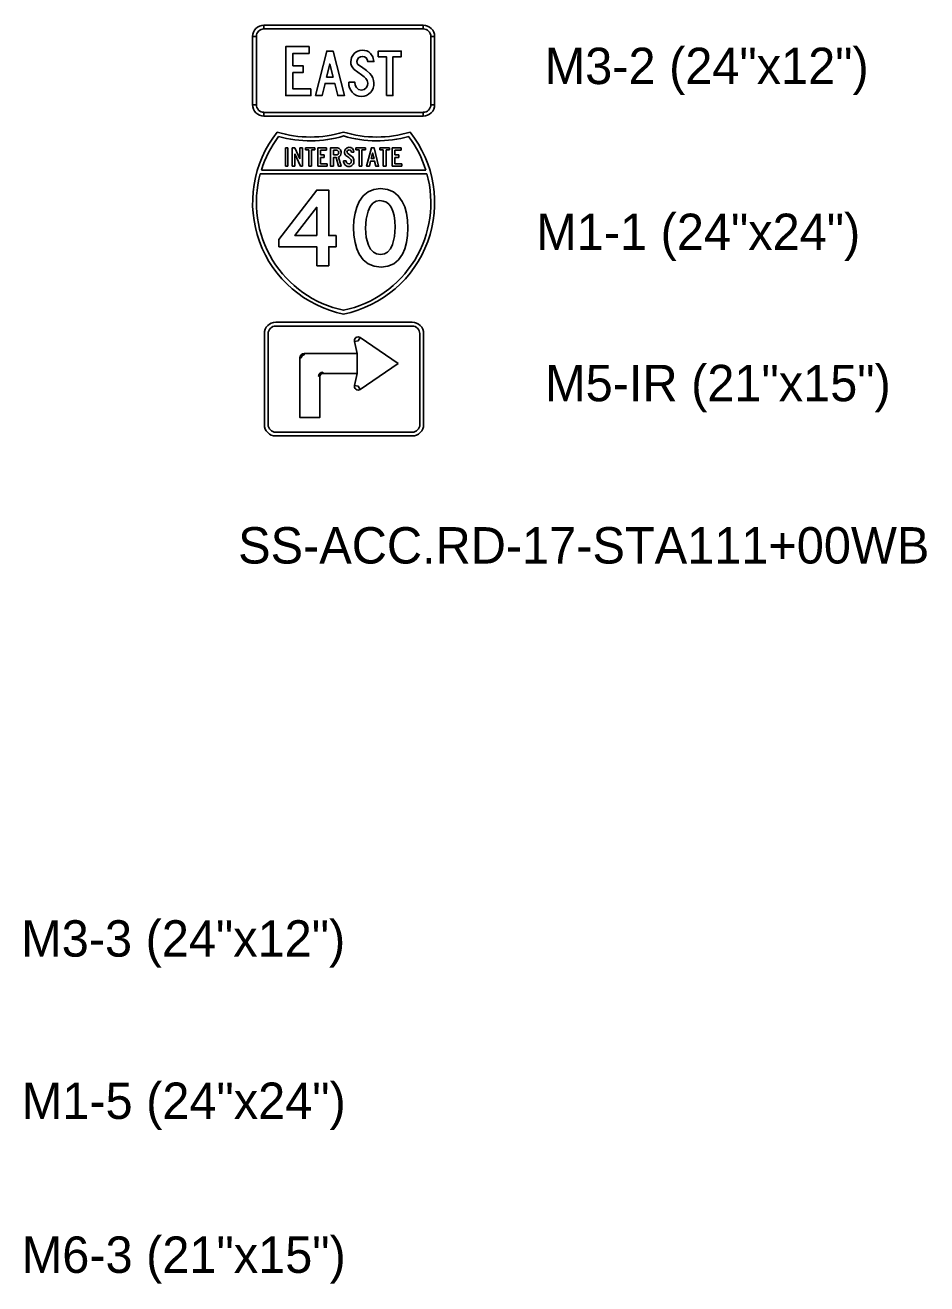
# Model space of a CAD drawing. Extents: x 620856.8 to 620948.6, y 415598.8 to 415658.2.
# Drawn here: x 620905.47 to 620915.37, y 415641.85 to 415655.69 of the extents above; entities that cross this region are included whole.
import ezdxf

# ---------------------------------------------------------------- set-up
doc = ezdxf.new("R2010")
doc.units = 0
doc.layers.add('SIGNS', color=7, linetype='Continuous')

msp = doc.modelspace()

# ---------------------------------------------------------------- linework, layer by layer
at = {"layer": 'SIGNS'}
for p, q in [((620908.089, 415655.647), (620908.089, 415655.689)), ((620909.839, 415655.689), (620909.839, 415655.647)), ((620907.964, 415655.564), (620908.006, 415655.564)), ((620909.922, 415655.564), (620909.964, 415655.564)), ((620908.006, 415654.814), (620907.964, 415654.814)), ((620909.964, 415654.814), (620909.922, 415654.814)), ((620908.089, 415654.689), (620908.089, 415654.73)), ((620909.839, 415654.73), (620909.839, 415654.689)), ((620908.352, 415654.342), (620908.324, 415654.342)), ((620908.324, 415654.342), (620908.324, 415654.138)), ((620908.352, 415654.138), (620908.352, 415654.342)), ((620908.427, 415654.342), (620908.399, 415654.342)), ((620908.399, 415654.342), (620908.399, 415654.138)), ((620908.483, 415654.221), (620908.427, 415654.342)), ((620908.427, 415654.138), (620908.427, 415654.276)), ((620908.427, 415654.276), (620908.491, 415654.138)), ((620908.514, 415654.342), (620908.483, 415654.342)), ((620908.483, 415654.342), (620908.483, 415654.221)), ((620908.514, 415654.138), (620908.514, 415654.342)), ((620908.649, 415654.342), (620908.544, 415654.342)), ((620908.544, 415654.342), (620908.544, 415654.317)), ((620908.544, 415654.317), (620908.582, 415654.317)), ((620908.582, 415654.317), (620908.582, 415654.138)), ((620908.611, 415654.138), (620908.611, 415654.317)), ((620908.611, 415654.317), (620908.649, 415654.317)), ((620908.649, 415654.317), (620908.649, 415654.342)), ((620908.777, 415654.342), (620908.68, 415654.342)), ((620908.68, 415654.342), (620908.68, 415654.138)), ((620908.71, 415654.262), (620908.71, 415654.314)), ((620908.71, 415654.314), (620908.777, 415654.314)), ((620908.752, 415654.262), (620908.71, 415654.262)), ((620908.752, 415654.234), (620908.752, 415654.262)), ((620908.777, 415654.314), (620908.777, 415654.342)), ((620908.976, 415654.313), (620908.972, 415654.294)), ((620908.972, 415654.294), (620908.973, 415654.283)), ((620908.973, 415654.283), (620908.976, 415654.274)), ((620908.988, 415654.331), (620908.976, 415654.313)), ((620908.976, 415654.274), (620908.981, 415654.265)), ((620908.981, 415654.265), (620908.988, 415654.257)), ((620908.996, 415654.338), (620908.988, 415654.331)), ((620908.988, 415654.257), (620909.021, 415654.234)), ((620909.005, 415654.342), (620908.996, 415654.338)), ((620909.001, 415654.294), (620909.003, 415654.304)), ((620909.002, 415654.288), (620909.001, 415654.294)), ((620909.005, 415654.282), (620909.002, 415654.288)), ((620909.003, 415654.304), (620909.008, 415654.311)), ((620909.014, 415654.345), (620909.005, 415654.342)), ((620909.021, 415654.27), (620909.005, 415654.282)), ((620909.008, 415654.311), (620909.016, 415654.316)), ((620909.025, 415654.346), (620909.014, 415654.345)), ((620909.016, 415654.316), (620909.026, 415654.318)), ((620909.045, 415654.254), (620909.021, 415654.27)), ((620909.036, 415654.345), (620909.025, 415654.346)), ((620909.026, 415654.318), (620909.036, 415654.316)), ((620909.046, 415654.343), (620909.036, 415654.345)), ((620909.036, 415654.316), (620909.043, 415654.312)), ((620909.043, 415654.312), (620909.047, 415654.305)), ((620909.06, 415654.24), (620909.045, 415654.254)), ((620909.055, 415654.338), (620909.046, 415654.343)), ((620909.047, 415654.305), (620909.05, 415654.294)), ((620909.05, 415654.294), (620909.078, 415654.294)), ((620909.063, 415654.332), (620909.055, 415654.338)), ((620909.074, 415654.315), (620909.063, 415654.332)), ((620909.078, 415654.294), (620909.074, 415654.315)), ((620909.204, 415654.342), (620909.099, 415654.342)), ((620909.099, 415654.342), (620909.099, 415654.317)), ((620909.099, 415654.317), (620909.136, 415654.317)), ((620909.136, 415654.317), (620909.136, 415654.138)), ((620909.165, 415654.138), (620909.165, 415654.317)), ((620909.165, 415654.317), (620909.204, 415654.317)), ((620909.204, 415654.317), (620909.204, 415654.342)), ((620909.468, 415654.342), (620909.363, 415654.342)), ((620909.363, 415654.342), (620909.363, 415654.317)), ((620909.363, 415654.317), (620909.4, 415654.317)), ((620909.4, 415654.317), (620909.4, 415654.138)), ((620909.43, 415654.138), (620909.43, 415654.317)), ((620909.43, 415654.317), (620909.468, 415654.317)), ((620909.468, 415654.317), (620909.468, 415654.342)), ((620909.596, 415654.342), (620909.499, 415654.342)), ((620909.499, 415654.342), (620909.499, 415654.138)), ((620909.528, 415654.262), (620909.528, 415654.314)), ((620909.528, 415654.314), (620909.596, 415654.314)), ((620909.571, 415654.262), (620909.528, 415654.262)), ((620909.571, 415654.234), (620909.571, 415654.262)), ((620909.596, 415654.314), (620909.596, 415654.342)), ((620908.324, 415654.138), (620908.352, 415654.138)), ((620908.399, 415654.138), (620908.427, 415654.138)), ((620908.491, 415654.138), (620908.514, 415654.138)), ((620908.582, 415654.138), (620908.611, 415654.138)), ((620908.68, 415654.138), (620908.785, 415654.138)), ((620908.71, 415654.166), (620908.71, 415654.234)), ((620908.71, 415654.234), (620908.752, 415654.234)), ((620908.785, 415654.166), (620908.71, 415654.166)), ((620908.785, 415654.138), (620908.785, 415654.166)), ((620908.991, 415654.199), (620908.963, 415654.199)), ((620908.963, 415654.199), (620908.963, 415654.198)), ((620908.963, 415654.198), (620908.964, 415654.185)), ((620908.964, 415654.185), (620908.967, 415654.174)), ((620908.967, 415654.174), (620908.972, 415654.163)), ((620908.972, 415654.163), (620908.979, 415654.153)), ((620908.979, 415654.153), (620908.988, 415654.145)), ((620908.988, 415654.145), (620908.998, 415654.139)), ((620908.993, 415654.186), (620908.991, 415654.199)), ((620908.999, 415654.175), (620908.993, 415654.186)), ((620908.998, 415654.139), (620909.009, 415654.135)), ((620909.008, 415654.167), (620908.999, 415654.175)), ((620909.021, 415654.164), (620909.008, 415654.167)), ((620909.009, 415654.135), (620909.021, 415654.134)), ((620909.021, 415654.234), (620909.034, 415654.224)), ((620909.033, 415654.166), (620909.021, 415654.164)), ((620909.021, 415654.134), (620909.033, 415654.135)), ((620909.042, 415654.174), (620909.033, 415654.166)), ((620909.033, 415654.135), (620909.044, 415654.139)), ((620909.034, 415654.224), (620909.041, 415654.217)), ((620909.041, 415654.217), (620909.048, 415654.207)), ((620909.048, 415654.184), (620909.042, 415654.174)), ((620909.044, 415654.139), (620909.054, 415654.145)), ((620909.048, 415654.207), (620909.05, 415654.196)), ((620909.05, 415654.196), (620909.048, 415654.184)), ((620909.054, 415654.145), (620909.063, 415654.153)), ((620909.068, 415654.23), (620909.06, 415654.24)), ((620909.063, 415654.153), (620909.07, 415654.162)), ((620909.074, 415654.22), (620909.068, 415654.23)), ((620909.07, 415654.162), (620909.075, 415654.173)), ((620909.077, 415654.208), (620909.074, 415654.22)), ((620909.075, 415654.173), (620909.077, 415654.184)), ((620909.078, 415654.196), (620909.077, 415654.208)), ((620909.077, 415654.184), (620909.078, 415654.196)), ((620909.136, 415654.138), (620909.165, 415654.138)), ((620909.4, 415654.138), (620909.43, 415654.138)), ((620909.499, 415654.138), (620909.604, 415654.138)), ((620909.528, 415654.166), (620909.528, 415654.234)), ((620909.528, 415654.234), (620909.571, 415654.234)), ((620909.604, 415654.166), (620909.528, 415654.166)), ((620909.604, 415654.138), (620909.604, 415654.166)), ((620909.868, 415654.096), (620908.06, 415654.096)), ((620909.718, 415652.423), (620908.218, 415652.423)), ((620908.218, 415652.423), (620908.218, 415652.423)), ((620908.218, 415652.381), (620909.718, 415652.381)), ((620908.093, 415652.298), (620908.093, 415651.298)), ((620908.135, 415651.298), (620908.135, 415652.298)), ((620909.084, 415652.21), (620909.124, 415652.22)), ((620909.124, 415652.22), (620909.147, 415652.255)), ((620909.801, 415652.298), (620909.801, 415651.298)), ((620909.843, 415651.298), (620909.843, 415652.298)), ((620908.484, 415652.032), (620908.497, 415652.032)), ((620908.531, 415652.065), (620908.531, 415652.079)), ((620908.689, 415651.829), (620908.702, 415651.829)), ((620908.734, 415651.86), (620908.734, 415651.873)), ((620909.124, 415651.72), (620909.084, 415651.729)), ((620909.147, 415651.684), (620909.124, 415651.72)), ((620909.718, 415651.214), (620908.218, 415651.214)), ((620908.218, 415651.173), (620909.718, 415651.173)), ((620909.718, 415651.173), (620909.718, 415651.173))]:
    msp.add_line(p, q, dxfattribs=at)
for points in [[(620909.839, 415655.689), (620908.089, 415655.689), (620908.089, 415655.647), (620909.839, 415655.647), (620909.839, 415655.689), (620909.839, 415655.689)], [(620907.964, 415655.564), (620907.964, 415654.814), (620908.006, 415654.814), (620908.006, 415655.564), (620907.964, 415655.564), (620907.964, 415655.564)], [(620909.964, 415654.814), (620909.964, 415655.564), (620909.922, 415655.564), (620909.922, 415654.814), (620909.964, 415654.814), (620909.964, 415654.814)], [(620908.605, 415654.988), (620908.407, 415654.988), (620908.407, 415655.167), (620908.519, 415655.167), (620908.519, 415655.242), (620908.407, 415655.242), (620908.407, 415655.379), (620908.585, 415655.379), (620908.585, 415655.453), (620908.328, 415655.453), (620908.328, 415654.914), (620908.605, 415654.914)], [(620909.02, 415655.061), (620909.02, 415655.057), (620909.023, 415655.027), (620909.03, 415654.999), (620909.042, 415654.974), (620909.058, 415654.951), (620909.08, 415654.93), (620909.104, 415654.916), (620909.13, 415654.907), (620909.159, 415654.904), (620909.189, 415654.907), (620909.215, 415654.915), (620909.239, 415654.929), (620909.26, 415654.949), (620909.276, 415654.972), (620909.288, 415654.997), (620909.295, 415655.024), (620909.297, 415655.054), (620909.294, 415655.082), (620909.286, 415655.109), (620909.272, 415655.135), (620909.253, 415655.159), (620909.216, 415655.191), (620909.159, 415655.23), (620909.122, 415655.258), (620909.114, 415655.272), (620909.111, 415655.289), (620909.115, 415655.311), (620909.128, 415655.329), (620909.148, 415655.342), (620909.17, 415655.346), (620909.195, 415655.342), (620909.212, 415655.33), (620909.222, 415655.313), (620909.229, 415655.289), (620909.297, 415655.289), (620909.286, 415655.339), (620909.26, 415655.378), (620909.241, 415655.394), (620909.22, 415655.405), (620909.195, 415655.411), (620909.168, 415655.414), (620909.143, 415655.411), (620909.12, 415655.404), (620909.099, 415655.392), (620909.08, 415655.376), (620909.052, 415655.335), (620909.043, 415655.287), (620909.045, 415655.262), (620909.052, 415655.24), (620909.064, 415655.219), (620909.08, 415655.2), (620909.16, 415655.143), (620909.189, 415655.12), (620909.208, 415655.104), (620909.224, 415655.079), (620909.23, 415655.053), (620909.225, 415655.024), (620909.211, 415654.999), (620909.188, 415654.981), (620909.159, 415654.975), (620909.129, 415654.982), (620909.106, 415655.002), (620909.092, 415655.029), (620909.088, 415655.061)], [(620909.435, 415654.914), (620909.506, 415654.914), (620909.506, 415655.342), (620909.598, 415655.342), (620909.598, 415655.404), (620909.345, 415655.404), (620909.345, 415655.342), (620909.435, 415655.342)], [(620908.089, 415654.689), (620909.839, 415654.689), (620909.839, 415654.73), (620908.089, 415654.73), (620908.089, 415654.689), (620908.089, 415654.689)], [(620909.562, 415651.97), (620909.147, 415652.255), (620909.124, 415652.22), (620909.084, 415652.21), (620909.114, 415652.079), (620909.114, 415651.86), (620909.084, 415651.729), (620909.124, 415651.72), (620909.147, 415651.684), (620909.562, 415651.97), (620909.562, 415651.97)], [(620908.702, 415651.376), (620908.484, 415651.376), (620908.484, 415652.032), (620908.531, 415652.079), (620909.114, 415652.079), (620909.114, 415651.86), (620908.734, 415651.86), (620908.702, 415651.86), (620908.702, 415651.829), (620908.702, 415651.376), (620908.702, 415651.376)]]:
    msp.add_lwpolyline(points, close=True, dxfattribs=at)
for points in [[(620908.655, 415654.914), (620908.727, 415654.914), (620908.76, 415655.049), (620908.866, 415655.049), (620908.9, 415654.914), (620908.972, 415654.914), (620908.848, 415655.404), (620908.779, 415655.404), (620908.655, 415654.914)], [(620908.777, 415655.118), (620908.812, 415655.261), (620908.848, 415655.118), (620908.777, 415655.118)], [(620908.234, 415654.513), (620908.234, 415654.513)], [(620908.249, 415654.465), (620908.249, 415654.465)], [(620908.964, 415654.471), (620908.964, 415654.471)], [(620909.679, 415654.465), (620909.679, 415654.465)], [(620909.695, 415654.513), (620909.695, 415654.513)], [(620908.853, 415654.138), (620908.853, 415654.235), (620908.881, 415654.235), (620908.908, 415654.138), (620908.937, 415654.138), (620908.907, 415654.239), (620908.92, 415654.246), (620908.929, 415654.257), (620908.935, 415654.27), (620908.937, 415654.285), (620908.936, 415654.297), (620908.933, 415654.308), (620908.929, 415654.318), (620908.923, 415654.326), (620908.915, 415654.333), (620908.906, 415654.338), (620908.895, 415654.341), (620908.883, 415654.342), (620908.821, 415654.342), (620908.821, 415654.138), (620908.853, 415654.138)], [(620908.853, 415654.262), (620908.853, 415654.314), (620908.883, 415654.314), (620908.894, 415654.313), (620908.902, 415654.307), (620908.908, 415654.299), (620908.91, 415654.288), (620908.908, 415654.277), (620908.903, 415654.269), (620908.895, 415654.264), (620908.884, 415654.262), (620908.853, 415654.262)], [(620909.247, 415654.138), (620909.261, 415654.194), (620909.305, 415654.194), (620909.319, 415654.138), (620909.349, 415654.138), (620909.298, 415654.342), (620909.269, 415654.342), (620909.217, 415654.138), (620909.247, 415654.138)], [(620909.268, 415654.223), (620909.282, 415654.283), (620909.298, 415654.223), (620909.268, 415654.223)], [(620908.048, 415654.055), (620908.591, 415654.055), (620909.118, 415654.055), (620909.88, 415654.055)], [(620908.669, 415653.045), (620908.801, 415653.045), (620908.801, 415653.254), (620908.881, 415653.254), (620908.881, 415653.375), (620908.801, 415653.375), (620908.801, 415653.876), (620908.669, 415653.876), (620908.253, 415653.333), (620908.253, 415653.254), (620908.669, 415653.254), (620908.669, 415653.045)], [(620909.368, 415653.892), (620909.295, 415653.883), (620909.233, 415653.856), (620909.18, 415653.812), (620909.136, 415653.75), (620909.109, 415653.689), (620909.09, 415653.621), (620909.078, 415653.546), (620909.074, 415653.464), (620909.078, 415653.379), (620909.09, 415653.301), (620909.109, 415653.232), (620909.136, 415653.171), (620909.18, 415653.109), (620909.235, 415653.064), (620909.3, 415653.038), (620909.376, 415653.029), (620909.45, 415653.038), (620909.514, 415653.065), (620909.567, 415653.11), (620909.61, 415653.173), (620909.636, 415653.232), (620909.654, 415653.3), (620909.665, 415653.376), (620909.669, 415653.459), (620909.665, 415653.546), (620909.654, 415653.623), (620909.635, 415653.692), (620909.609, 415653.751), (620909.565, 415653.813), (620909.511, 415653.857), (620909.445, 415653.883), (620909.368, 415653.892)], [(620909.53, 415653.468), (620909.523, 415653.365), (620909.501, 415653.279), (620909.478, 415653.23), (620909.448, 415653.195), (620909.412, 415653.175), (620909.371, 415653.168), (620909.327, 415653.174), (620909.291, 415653.194), (620909.26, 415653.226), (620909.236, 415653.271), (620909.212, 415653.356), (620909.204, 415653.456), (620909.212, 415653.556), (620909.234, 415653.645), (620909.257, 415653.695), (620909.286, 415653.731), (620909.32, 415653.753), (620909.361, 415653.76), (620909.4, 415653.756), (620909.435, 415653.742), (620909.464, 415653.719), (620909.488, 415653.687), (620909.506, 415653.646), (620909.519, 415653.596), (620909.527, 415653.536), (620909.53, 415653.468)], [(620908.669, 415653.375), (620908.429, 415653.375), (620908.669, 415653.688), (620908.669, 415653.375)], [(620908.964, 415652.555), (620908.964, 415652.555)], [(620908.964, 415652.513), (620908.964, 415652.513)], [(620909.718, 415652.423), (620909.718, 415652.423)], [(620909.843, 415652.298), (620909.843, 415652.298)], [(620908.093, 415651.298), (620908.093, 415651.298)], [(620908.218, 415651.173), (620908.218, 415651.173)]]:
    msp.add_lwpolyline(points, dxfattribs=at)
for centre, radius, start, end in [((620908.089, 415655.564), 0.125, 90.0002, 179.9998), ((620908.089, 415655.564), 0.0833, 90.0002, 179.9998), ((620909.839, 415655.564), 0.125, 0, 90.0002), ((620909.839, 415655.564), 0.0833, 0, 90.0002), ((620908.089, 415654.814), 0.125, 179.9998, 270.0001), ((620908.089, 415654.814), 0.0833, 179.9998, 270.0001), ((620909.839, 415654.814), 0.125, 270.0001, 0.0003), ((620909.839, 415654.814), 0.0833, 270.0001, 0.0003), ((620909.214, 415653.738), 1.25, 141.669, 258.463), ((620909.214, 415653.737), 1.208, 142.9959, 162.6952), ((620908.599, 415655.709), 1.25, 253.009, 286.9909), ((620908.596, 415655.709), 1.292, 254.4391, 286.5746), ((620908.714, 415653.738), 1.25, 281.5371, 38.3311), ((620909.329, 415655.709), 1.25, 253.0091, 286.9911), ((620909.333, 415655.709), 1.292, 253.4255, 285.561), ((620908.714, 415653.737), 1.208, 17.3047, 37.0041), ((620909.214, 415653.737), 1.208, 164.7534, 258.0704), ((620908.714, 415653.737), 1.208, 281.9296, 15.2467), ((620908.714, 415653.737), 1.208, 281.92961267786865, 281.9296393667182), ((620909.214, 415653.737), 1.208, 258.0704, 258.0705), ((620908.218, 415652.298), 0.125, 90, 180), ((620908.218, 415652.298), 0.0833, 89.9998, 180), ((620909.718, 415652.298), 0.125, 0.0002, 89.9998), ((620909.718, 415652.298), 0.0833, 0.0002, 89.9998), ((620909.124, 415652.22), 0.0417, 57.7244, 192.9504), ((620908.531, 415652.032), 0.0469, 90.0002, 179.9998), ((620908.531, 415652.032), 0.0332, 90.0002, 179.9998), ((620908.734, 415651.829), 0.0442, 90.0002, 179.9998), ((620908.734, 415651.829), 0.0312, 90.0002, 179.9998), ((620909.124, 415651.72), 0.0417, 167.0499, 302.2759), ((620908.218, 415651.298), 0.125, 180, 269.9999), ((620908.218, 415651.298), 0.0833, 179.9997, 269.9999), ((620909.718, 415651.298), 0.125, 270, 0.0002), ((620909.718, 415651.298), 0.0833, 269.9999, 0.0002)]:
    msp.add_arc(centre, radius, start, end, dxfattribs=at)

# ---------------------------------------------------------------- texts
for s, p in [('M3-2 (24"x12")', (620911.173, 415655.041)), ('M1-1 (24"x24")', (620911.08, 415653.217)), ('M5-IR (21"x15")', (620911.178, 415651.555)), ('SS-ACC.RD-17-STA111+00WB', (620907.805, 415649.771)), ('M3-3 (24"x12")', (620905.421, 415645.45)), ('M1-5 (24"x24")', (620905.427, 415643.666)), ('M6-3 (21"x15")', (620905.427, 415641.974))]:
    msp.add_text(s, height=0.4, rotation=0, dxfattribs=at).set_placement(p)

doc.saveas('drawing.dxf')
